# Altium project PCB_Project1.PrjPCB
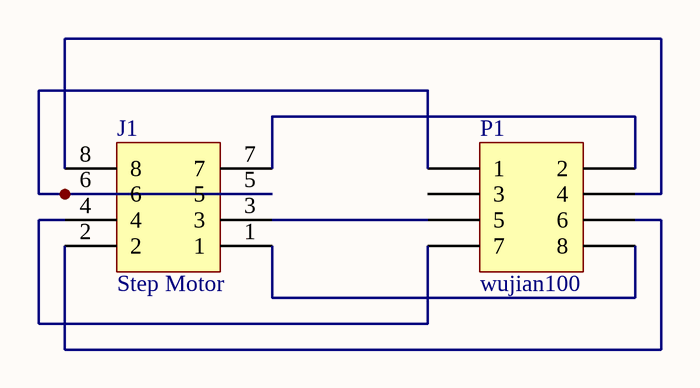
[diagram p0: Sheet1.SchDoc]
1 sheet, 2 parts. Net scope: global (net labels, ports and power ports of the same name join across sheets).
Board file: PCB1.PcbDoc

## Sheet Sheet1.SchDoc
size A3

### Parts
J1  Pin HDR2X4  [Pin HDR2X4/2.54mm-S]  (value not drawn)
P1  MHDR2X4  [MHDR2X4]  (value not drawn)

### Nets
NetJ1_1: J1.1 P1.8
NetJ1_2: J1.2 P1.6
NetJ1_3: J1.3 P1.5
NetJ1_4: J1.4 P1.7
NetJ1_5: J1.5 J1.6 P1.1
NetJ1_7: J1.7 P1.2
NetJ1_8: J1.8 P1.4

Not connected (* = marked no-connect by the designer): P1 3

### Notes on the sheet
- (near J1) Step Motor
- (near P1) wujian100

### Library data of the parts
P1 = MHDR2X4: Header, 4-Pin, Dual row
